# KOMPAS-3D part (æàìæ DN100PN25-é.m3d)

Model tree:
1. Объединить компоненты:1  (labels: СЕНС DN100PN25-В)

Referenced files in D:\Савин\!СЕНСОР\3D для заказчика\!Новый перечень\СЕНС\3. СЕНС-В\DN100\: СЕНС DN100PN25-В.a3d
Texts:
  СЕНС DN100PN25-В
  ООО НПП Сенсор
